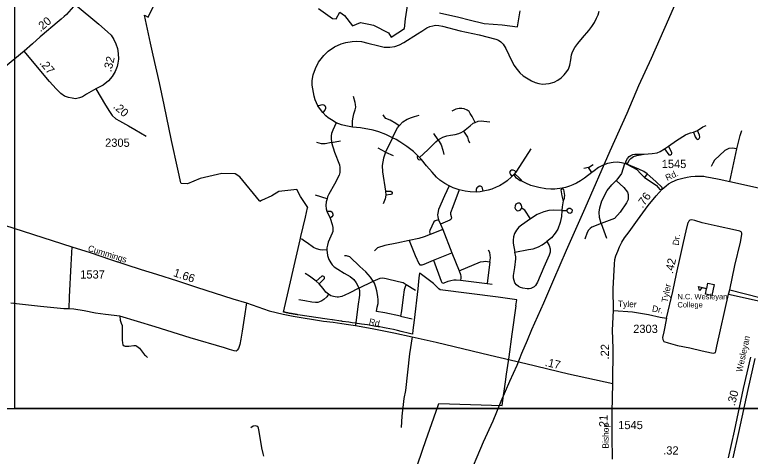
# Model space of a CAD drawing. Extents: x 2220236 to 2384410, y 720751 to 894131.
# Drawn here: x 2352246 to 2363367, y 825303 to 831981 of the extents above; entities that cross this region are included whole.
import ezdxf

# ---------------------------------------------------------------- set-up
doc = ezdxf.new("R2010")
doc.units = 0
doc.layers.add('Default', color=7, linetype='Continuous')

msp = doc.modelspace()

# ---------------------------------------------------------------- linework, layer by layer
at = {"layer": 'Default'}
for p, q in [((2358650, 830088), (2358582, 830185)), ((2362506, 830206), (2362567, 830229)), ((2357038, 830048), (2357173, 830075)), ((2357960, 830119), (2357854, 829904)), ((2357854, 829904), (2357741, 829962)), ((2362069, 829951), (2362128, 829994)), ((2363057, 829458), (2363161, 829951)), ((2357854, 829904), (2357966, 829850)), ((2358365, 829821), (2358338, 829850)), ((2358395, 829791), (2358365, 829821)), ((2360921, 829670), (2360992, 829716)), ((2359799, 829567), (2359828, 829601)), ((2360921, 829670), (2360848, 829653)), ((2360970, 829594), (2360921, 829670)), ((2359799, 829567), (2359759, 829528)), ((2361807, 829576), (2361765, 829519)), ((2356970, 829199), (2356796, 829253)), ((2357851, 829311), (2357855, 829250)), ((2356967, 829008), (2357015, 828903)), ((2360519, 829021), (2360594, 829019)), ((2358654, 828881), (2358685, 828815)), ((2358685, 828815), (2358717, 828732)), ((2361113, 828826), (2361192, 828601)), ((2358717, 828732), (2358527, 828659)), ((2358717, 828732), (2358857, 828379)), ((2358577, 828268), (2358857, 828379)), ((2358857, 828379), (2358968, 828106)), ((2359431, 828244), (2359387, 827916)), ((2356849, 827909), (2356805, 827951)), ((2357447, 827845), (2357666, 827953)), ((2358988, 827965), (2359387, 827916)), ((2359387, 827916), (2359463, 827904)), ((2358164, 827903), (2358305, 827817)), ((2363039, 827756), (2363055, 827818)), ((2363055, 827818), (2363513, 827702)), ((2363039, 827756), (2363559, 827639)), ((2358078, 827422), (2358257, 827382))]:
    msp.add_line(p, q, dxfattribs=at)
for points in [[(2352250, 836556), (2366536, 836556), (2366536, 826026), (2352250, 826026), (2352250, 836556)], [(2358330, 825160), (2358413, 825397), (2358464, 825542), (2358523, 825713), (2358584, 825885), (2358658, 826099), (2359614, 826072), (2359636, 826221), (2359651, 826325), (2359666, 826429), (2359682, 826544), (2359711, 826744), (2359720, 826805), (2359767, 827152), (2359826, 827580), (2359823, 827580), (2359836, 827667), (2359553, 827708), (2358676, 827819), (2358658, 827837), (2358579, 827916), (2358376, 828067), (2358366, 828072), (2358358, 828004), (2358339, 827835), (2358284, 827362), (2358267, 827210), (2358260, 827150), (2358236, 827156), (2358217, 827160), (2358091, 827190), (2358034, 827204), (2357971, 827220), (2357918, 827231), (2357860, 827243), (2357814, 827252), (2357764, 827260), (2357743, 827263), (2357708, 827268), (2357580, 827289), (2357489, 827302), (2357391, 827316), (2357346, 827323), (2357300, 827330), (2357201, 827344), (2357193, 827345), (2357177, 827347), (2357049, 827366), (2357046, 827366), (2356969, 827377), (2356529, 827443), (2356526, 827444), (2356522, 827444), (2356518, 827445), (2356515, 827445), (2356512, 827446), (2356508, 827446), (2356505, 827447), (2356501, 827447), (2356498, 827448), (2356494, 827449), (2356491, 827449), (2356488, 827450), (2356484, 827450), (2356480, 827451), (2356477, 827451), (2356474, 827452), (2356470, 827453), (2356467, 827453), (2356463, 827454), (2356460, 827454), (2356456, 827455), (2356453, 827456), (2356450, 827456), (2356446, 827457), (2356443, 827457), (2356439, 827458), (2356436, 827459), (2356432, 827459), (2356429, 827460), (2356426, 827461), (2356422, 827461), (2356418, 827462), (2356415, 827463), (2356412, 827463), (2356408, 827464), (2356405, 827465), (2356402, 827465), (2356398, 827466), (2356394, 827467), (2356391, 827467), (2356388, 827468), (2356384, 827469), (2356381, 827470), (2356378, 827470), (2356374, 827471), (2356370, 827472), (2356367, 827472), (2356364, 827473), (2356360, 827474), (2356357, 827475), (2356354, 827475), (2356350, 827476), (2356346, 827477), (2356343, 827478), (2356340, 827478), (2356336, 827479), (2356333, 827480), (2356330, 827481), (2356326, 827482), (2356323, 827482), (2356319, 827483), (2356316, 827484), (2356312, 827485), (2356311, 827485), (2356563, 828577), (2356574, 828626), (2356642, 828919), (2356674, 829060), (2356676, 829066), (2356676, 829068), (2356566, 829230), (2356565, 829232), (2356510, 829340), (2356241, 829305), (2356133, 829244), (2355978, 829170), (2355954, 829158), (2355947, 829166), (2355648, 829528), (2355580, 829574), (2355377, 829581), (2355048, 829504), (2354858, 829424), (2354762, 829429), (2354760, 829437), (2354714, 829646), (2354618, 830080), (2354505, 830617), (2354434, 830953), (2354340, 831367), (2354300, 831549), (2354206, 831974), (2354263, 831946), (2355002, 833447)], [(2358330, 825160), (2358413, 825397), (2358464, 825542), (2358523, 825713), (2358584, 825885), (2358658, 826099), (2359614, 826072), (2359636, 826221), (2359651, 826325), (2359666, 826429), (2359682, 826544), (2359711, 826744), (2359720, 826805), (2359767, 827152), (2359826, 827580), (2359823, 827580), (2359836, 827667), (2359553, 827708), (2358676, 827819), (2358658, 827837), (2358579, 827916), (2358376, 828067), (2358366, 828072), (2358358, 828004), (2358339, 827835), (2358284, 827362), (2358267, 827210), (2358260, 827150), (2358236, 827156), (2358217, 827160), (2358091, 827190), (2358034, 827204), (2357971, 827220), (2357918, 827231), (2357860, 827243), (2357814, 827252), (2357764, 827260), (2357743, 827263), (2357708, 827268), (2357580, 827289), (2357489, 827302), (2357391, 827316), (2357346, 827323), (2357300, 827330), (2357201, 827344), (2357193, 827345), (2357177, 827347), (2357049, 827366), (2357046, 827366), (2356969, 827377), (2356529, 827443), (2356526, 827444), (2356522, 827444), (2356518, 827445), (2356515, 827445), (2356512, 827446), (2356508, 827446), (2356505, 827447), (2356501, 827447), (2356498, 827448), (2356494, 827449), (2356491, 827449), (2356488, 827450), (2356484, 827450), (2356480, 827451), (2356477, 827451), (2356474, 827452), (2356470, 827453), (2356467, 827453), (2356463, 827454), (2356460, 827454), (2356456, 827455), (2356453, 827456), (2356450, 827456), (2356446, 827457), (2356443, 827457), (2356439, 827458), (2356436, 827459), (2356432, 827459), (2356429, 827460), (2356426, 827461), (2356422, 827461), (2356418, 827462), (2356415, 827463), (2356412, 827463), (2356408, 827464), (2356405, 827465), (2356402, 827465), (2356398, 827466), (2356394, 827467), (2356391, 827467), (2356388, 827468), (2356384, 827469), (2356381, 827470), (2356378, 827470), (2356374, 827471), (2356370, 827472), (2356367, 827472), (2356364, 827473), (2356360, 827474), (2356357, 827475), (2356354, 827475), (2356350, 827476), (2356346, 827477), (2356343, 827478), (2356340, 827478), (2356336, 827479), (2356333, 827480), (2356330, 827481), (2356326, 827482), (2356323, 827482), (2356319, 827483), (2356316, 827484), (2356312, 827485), (2356311, 827485), (2356563, 828577), (2356574, 828626), (2356642, 828919), (2356674, 829060), (2356676, 829066), (2356676, 829068), (2356566, 829230), (2356565, 829232), (2356510, 829340), (2356241, 829305), (2356133, 829244), (2355978, 829170), (2355954, 829158), (2355947, 829166), (2355648, 829528), (2355580, 829574), (2355377, 829581), (2355048, 829504), (2354858, 829424), (2354762, 829429), (2354760, 829437), (2354714, 829646), (2354618, 830080), (2354505, 830617), (2354434, 830953), (2354340, 831367), (2354300, 831549), (2354206, 831974), (2354263, 831946), (2355002, 833447)], [(2362323, 832356), (2362132, 831914), (2361866, 831321), (2361677, 830903), (2361500, 830489), (2361243, 829918), (2360865, 829050), (2360583, 828413), (2360390, 827970), (2360239, 827619), (2360058, 827213), (2359995, 827052), (2359910, 826859), (2359836, 826678), (2359727, 826435), (2359593, 826131), (2359474, 825832), (2359330, 825515), (2359079, 824930)], [(2353159, 832136), (2353133, 832104), (2353027, 831984), (2352992, 831952), (2352948, 831913), (2352886, 831863), (2352661, 831673), (2352631, 831647), (2352514, 831539), (2352388, 831430)], [(2353159, 832136), (2353517, 831837), (2353651, 831724), (2353703, 831672), (2353745, 831607), (2353774, 831539), (2353799, 831471), (2353812, 831393), (2353817, 831310), (2353807, 831250), (2353794, 831196), (2353763, 831120), (2353721, 831049), (2353663, 830981), (2353582, 830917), (2353475, 830860)], [(2356831, 830601), (2356789, 830696), (2356772, 830748), (2356753, 830860), (2356745, 830915), (2356745, 830985), (2356756, 831073), (2356792, 831170), (2356841, 831261), (2356919, 831364), (2356984, 831431), (2357080, 831495), (2357181, 831539), (2357252, 831560), (2357348, 831575), (2357415, 831580), (2357490, 831574), (2357586, 831549), (2357753, 831510), (2357832, 831492), (2357874, 831490), (2357916, 831492), (2357992, 831499), (2358066, 831526), (2358127, 831561), (2358338, 831691), (2358400, 831731), (2358477, 831785), (2358522, 831804), (2358567, 831814), (2358606, 831821), (2358656, 831819), (2358714, 831806), (2358983, 831738), (2359270, 831675), (2359519, 831613), (2359558, 831595), (2359596, 831571), (2359633, 831533), (2359670, 831471), (2359715, 831373), (2359793, 831219), (2359840, 831150), (2359881, 831101), (2359933, 831057), (2360059, 830979), (2360116, 830955), (2360172, 830941), (2360226, 830931), (2360278, 830935), (2360324, 830940), (2360402, 830963), (2360458, 830990), (2360510, 831026), (2360555, 831074), (2360595, 831123), (2360617, 831157), (2360637, 831216), (2360655, 831299), (2360666, 831373), (2360681, 831420), (2360714, 831486), (2360759, 831545), (2360832, 831633), (2360927, 831744), (2360972, 831804), (2361012, 831865), (2361041, 831927), (2361069, 831979), (2361083, 832035)], [(2356840, 832077), (2357050, 831924), (2357106, 831918), (2357162, 832021), (2357230, 831970), (2357354, 831812), (2357474, 831864), (2357598, 831838), (2357670, 831822), (2357897, 831708), (2357935, 831640), (2358140, 831773), (2358156, 831921), (2358182, 832113)], [(2356840, 832077), (2357050, 831924), (2357106, 831918), (2357162, 832021), (2357230, 831970), (2357354, 831812), (2357474, 831864), (2357598, 831838), (2357670, 831822), (2357897, 831708), (2357935, 831640), (2358140, 831773), (2358156, 831921), (2358182, 832113)], [(2358668, 832007), (2358961, 831942), (2359118, 831904), (2359344, 831850), (2359616, 831826), (2359845, 831797), (2359886, 832038)], [(2358668, 832007), (2358961, 831942), (2359118, 831904), (2359344, 831850), (2359616, 831826), (2359845, 831797), (2359886, 832038)], [(2352388, 831430), (2352108, 831200), (2351948, 831058), (2351736, 830882), (2351559, 830720), (2351415, 830571)], [(2353475, 830860), (2353331, 830777), (2353271, 830741), (2353224, 830724), (2353166, 830710), (2353117, 830717), (2353060, 830728), (2352999, 830750), (2352945, 830789), (2352871, 830858), (2352773, 830973), (2352642, 831126), (2352546, 831245), (2352388, 831430)], [(2353475, 830860), (2353555, 830722), (2353602, 830638), (2353669, 830530), (2353720, 830459), (2353777, 830407), (2353829, 830375), (2353967, 830299), (2354062, 830247), (2354232, 830143)], [(2357352, 830280), (2357355, 830374), (2357362, 830430), (2357375, 830480), (2357394, 830543), (2357404, 830584), (2357399, 830621), (2357393, 830654), (2357368, 830744)], [(2356831, 830601), (2356879, 830619), (2356899, 830625), (2356921, 830620), (2356936, 830608), (2356946, 830583), (2356946, 830561), (2356936, 830539), (2356902, 830501)], [(2356902, 830501), (2356867, 830546), (2356831, 830601)], [(2357108, 830345), (2357033, 830389), (2356983, 830423), (2356949, 830452), (2356902, 830501)], [(2359205, 830352), (2359163, 830440), (2359134, 830485), (2359117, 830516), (2359084, 830536), (2359043, 830556), (2359007, 830565), (2358965, 830563), (2358916, 830554), (2358855, 830522)], [(2358058, 830302), (2358010, 830337), (2357920, 830385), (2357857, 830410), (2357839, 830437), (2357815, 830468)], [(2358058, 830302), (2358116, 830359), (2358180, 830402), (2358244, 830429), (2358288, 830444), (2358359, 830462)], [(2359205, 830352), (2359252, 830370), (2359299, 830376), (2359338, 830373), (2359428, 830360)], [(2357108, 830345), (2357057, 830236), (2357037, 830186), (2357030, 830147), (2357028, 830113), (2357038, 830048)], [(2357352, 830280), (2357251, 830299), (2357186, 830314), (2357108, 830345)], [(2357960, 830119), (2357859, 830168), (2357753, 830209), (2357665, 830233), (2357472, 830270), (2357352, 830280)], [(2357960, 830119), (2358009, 830223), (2358034, 830268), (2358058, 830302)], [(2359029, 830219), (2359132, 830303), (2359179, 830341), (2359205, 830352)], [(2362567, 830229), (2362648, 830283), (2362699, 830308)], [(2358650, 830088), (2358717, 830128), (2358781, 830148), (2358836, 830160), (2358905, 830169), (2358960, 830185), (2358995, 830198), (2359029, 830219)], [(2359029, 830219), (2359091, 830127), (2359103, 830091), (2359120, 830042)], [(2362128, 829994), (2362252, 830078), (2362388, 830164), (2362420, 830181), (2362461, 830196), (2362506, 830206)], [(2362506, 830206), (2362532, 830136), (2362555, 830102), (2362572, 830096), (2362584, 830100), (2362596, 830111), (2362603, 830128), (2362597, 830161), (2362567, 830229)], [(2363161, 829951), (2363213, 830156), (2363237, 830230)], [(2357038, 830048), (2356938, 830030), (2356883, 830030), (2356812, 830050)], [(2357038, 830048), (2357082, 829904), (2357156, 829711), (2357161, 829671), (2357161, 829632), (2357161, 829593), (2357152, 829554), (2357082, 829416), (2356993, 829269), (2356976, 829228), (2356970, 829199)], [(2358338, 829850), (2358274, 829913), (2358176, 829987), (2358068, 830060), (2358012, 830093), (2357960, 830119)], [(2358365, 829821), (2358492, 829940), (2358613, 830061), (2358650, 830088)], [(2358650, 830088), (2358692, 830013), (2358717, 829935), (2358734, 829869)], [(2359828, 829601), (2359884, 829685), (2360055, 829953)], [(2361763, 829870), (2361883, 829881), (2361960, 829893), (2362004, 829911), (2362069, 829951)], [(2362069, 829951), (2362134, 829862), (2362159, 829862), (2362174, 829874), (2362182, 829884), (2362182, 829895), (2362128, 829994)], [(2363161, 829951), (2363094, 829962), (2363043, 829956), (2362983, 829927), (2362824, 829781), (2362798, 829737), (2362775, 829683)], [(2357854, 829904), (2357821, 829810), (2357802, 829701), (2357808, 829605), (2357851, 829311)], [(2358338, 829850), (2358331, 829826), (2358338, 829806), (2358350, 829789), (2358362, 829787), (2358395, 829791)], [(2361499, 829721), (2361486, 829748), (2361486, 829763), (2361508, 829804), (2361537, 829837), (2361559, 829854), (2361589, 829866), (2361621, 829873), (2361680, 829873), (2361763, 829870)], [(2361499, 829721), (2361517, 829738), (2361538, 829782), (2361563, 829809), (2361602, 829835), (2361653, 829851), (2361763, 829870)], [(2358813, 829391), (2358750, 829430), (2358675, 829479), (2358623, 829526), (2358555, 829599), (2358474, 829697), (2358395, 829791)], [(2361499, 829721), (2361445, 829736), (2361364, 829752), (2361295, 829745), (2361209, 829732), (2361145, 829708), (2361072, 829669), (2361004, 829622), (2360970, 829594)], [(2361466, 829726), (2361422, 829580), (2361363, 829504), (2361341, 829475)], [(2361807, 829576), (2361759, 829608), (2361684, 829646), (2361499, 829721)], [(2361499, 829721), (2361649, 829638), (2361712, 829574), (2361744, 829542), (2361765, 829519)], [(2359828, 829601), (2359807, 829622), (2359781, 829631), (2359758, 829629), (2359740, 829619), (2359728, 829599), (2359730, 829584), (2359740, 829567), (2359750, 829549), (2359759, 829528)], [(2360970, 829594), (2360862, 829511), (2360798, 829467), (2360739, 829431), (2360685, 829407), (2360632, 829389), (2360573, 829369), (2360522, 829356)], [(2359759, 829528), (2359693, 829469), (2359640, 829431), (2359575, 829394), (2359527, 829373), (2359460, 829345), (2359403, 829327), (2359329, 829313)], [(2359914, 829466), (2359907, 829480), (2359870, 829521), (2359818, 829564), (2359799, 829567)], [(2359914, 829466), (2359890, 829471), (2359834, 829511), (2359807, 829538), (2359799, 829567)], [(2361113, 828826), (2361089, 828915), (2361084, 828994), (2361093, 829060), (2361122, 829165), (2361201, 829324), (2361272, 829407), (2361341, 829475)], [(2361341, 829475), (2361455, 829369), (2361511, 829299), (2361522, 829261), (2361522, 829188), (2361497, 829136), (2361402, 828996), (2361312, 828897), (2361272, 828882), (2361113, 828826)], [(2361301, 827510), (2361294, 827837), (2361314, 828209), (2361320, 828278), (2361336, 828333), (2361362, 828406), (2361388, 828471), (2361426, 828540), (2361466, 828609), (2361534, 828697), (2361662, 828875), (2361821, 829098), (2361943, 829242), (2362032, 829343), (2362094, 829394), (2362132, 829422), (2362188, 829453), (2362267, 829488), (2362349, 829511), (2362411, 829525), (2362467, 829532), (2362533, 829539), (2362578, 829539), (2362614, 829540), (2362664, 829538), (2362704, 829530), (2362766, 829520), (2362897, 829494), (2363057, 829458), (2363853, 829280)], [(2361765, 829519), (2361868, 829455), (2361948, 829398), (2361997, 829340), (2362032, 829343)], [(2362032, 829343), (2362032, 829366), (2361937, 829460), (2361855, 829536), (2361807, 829576)], [(2358813, 829391), (2358742, 829244), (2358654, 829036), (2358642, 828982), (2358639, 828956), (2358641, 828926), (2358654, 828881)], [(2358965, 829331), (2358877, 829364), (2358813, 829391)], [(2359329, 829313), (2359320, 829356), (2359307, 829377), (2359290, 829387), (2359268, 829387), (2359246, 829375), (2359232, 829363), (2359222, 829338), (2359225, 829298)], [(2360522, 829356), (2360413, 829343), (2360349, 829343), (2360276, 829350), (2360170, 829368), (2360051, 829397), (2359973, 829431), (2359914, 829466)], [(2357855, 829250), (2357848, 829195), (2357816, 829123)], [(2357851, 829311), (2357934, 829313), (2357951, 829297), (2357955, 829281), (2357949, 829269), (2357934, 829262), (2357855, 829250)], [(2358965, 829331), (2358869, 829074), (2358836, 828986), (2358834, 828965), (2358846, 828927), (2358850, 828905), (2358841, 828886), (2358823, 828873), (2358685, 828815)], [(2359225, 829298), (2359133, 829303), (2359057, 829310), (2358965, 829331)], [(2359329, 829313), (2359281, 829304), (2359225, 829298)], [(2360522, 829356), (2360502, 829335), (2360519, 829240), (2360531, 829183), (2360539, 829167)], [(2360522, 829356), (2360541, 829339), (2360556, 829249), (2360554, 829224), (2360551, 829198), (2360539, 829167)], [(2356970, 829199), (2356955, 829150), (2356951, 829097), (2356957, 829045), (2356967, 829008)], [(2360539, 829167), (2360524, 829077), (2360519, 829021)], [(2360043, 828892), (2359960, 829023), (2359934, 829041), (2359911, 829054)], [(2360519, 829021), (2360388, 829025), (2360319, 829018), (2360248, 829001), (2360147, 828958), (2360043, 828892)], [(2356967, 829008), (2357002, 829011), (2357027, 829009), (2357047, 828994), (2357057, 828966), (2357057, 828947), (2357042, 828923), (2357015, 828903)], [(2360519, 829021), (2360513, 828929), (2360494, 828841), (2360456, 828740), (2360419, 828675), (2360359, 828608), (2360293, 828549)], [(2351931, 828849), (2353109, 828472), (2353387, 828383), (2353695, 828279), (2354158, 828130), (2354389, 828058), (2354709, 827954), (2354994, 827862), (2355545, 827685), (2355750, 827623), (2356092, 827503), (2356307, 827452), (2356456, 827420), (2356606, 827398), (2356764, 827373), (2356916, 827349), (2357061, 827330), (2357193, 827313), (2357292, 827297), (2357398, 827279), (2357651, 827238), (2357977, 827172), (2358253, 827112), (2358616, 827028), (2359432, 826831), (2359974, 826705), (2360617, 826552), (2361288, 826402)], [(2357015, 828903), (2357047, 828808), (2357054, 828761), (2357054, 828727), (2357054, 828705), (2357047, 828675), (2356987, 828543), (2356973, 828494), (2356965, 828458), (2356967, 828426)], [(2358654, 828881), (2358604, 828863), (2358582, 828848), (2358520, 828718), (2358516, 828695), (2358527, 828659)], [(2360043, 828892), (2359907, 828800), (2359870, 828767), (2359834, 828725), (2359804, 828673), (2359789, 828622), (2359784, 828573), (2359784, 828526), (2359809, 828390)], [(2361113, 828826), (2360973, 828770), (2360944, 828746), (2360919, 828723), (2360899, 828686), (2360863, 828587)], [(2361301, 827510), (2361586, 827490), (2361826, 827447), (2362002, 827408), (2362101, 827391), (2362196, 827797), (2362252, 828063), (2362305, 828310), (2362359, 828537), (2362399, 828711), (2362430, 828839)], [(2363055, 827818), (2363135, 828188), (2363217, 828541), (2363240, 828655), (2363238, 828677), (2363227, 828697), (2363207, 828707), (2363141, 828724), (2362868, 828783), (2362639, 828836), (2362527, 828868), (2362483, 828878), (2362454, 828875), (2362438, 828858), (2362430, 828839)], [(2356967, 828426), (2356904, 828421), (2356863, 828424), (2356808, 828441), (2356763, 828463), (2356670, 828532), (2356611, 828568), (2356580, 828593)], [(2358527, 828659), (2358437, 828620), (2358355, 828597), (2358209, 828568)], [(2353109, 828472), (2353094, 828197), (2353069, 827716), (2353067, 827534)], [(2358209, 828568), (2358021, 828528), (2357842, 828490), (2357731, 828454), (2357686, 828410)], [(2358209, 828568), (2358301, 828341), (2358358, 828217), (2358372, 828199), (2358404, 828196), (2358434, 828209), (2358577, 828268)], [(2360293, 828549), (2360325, 828492), (2360340, 828438), (2360340, 828388), (2360326, 828343), (2360245, 828161), (2360150, 827935), (2360118, 827886), (2360097, 827864), (2360069, 827849), (2360050, 827843), (2360023, 827837), (2359993, 827837), (2359927, 827845), (2359891, 827856), (2359864, 827871), (2359834, 827894), (2359809, 827928), (2359796, 827961), (2359788, 827995), (2359788, 828038), (2359805, 828160), (2359821, 828291), (2359821, 828320), (2359809, 828390)], [(2359809, 828390), (2360013, 828428), (2360085, 828442), (2360166, 828470), (2360220, 828500), (2360293, 828549)], [(2356967, 828426), (2356975, 828341), (2356995, 828279), (2357025, 828230), (2357047, 828199), (2357078, 828169), (2357130, 828132), (2357225, 828073), (2357318, 828020), (2357371, 827978), (2357410, 827928), (2357427, 827890), (2357447, 827845)], [(2359431, 828244), (2359439, 828302), (2359436, 828345), (2359427, 828385), (2359410, 828419)], [(2357666, 827953), (2357625, 828013), (2357554, 828094), (2357466, 828175), (2357313, 828318), (2357264, 828333), (2357232, 828335)], [(2358577, 828268), (2358694, 827949), (2358705, 827932), (2358722, 827922), (2358738, 827924), (2358801, 827949), (2358840, 827963), (2358885, 827970), (2358921, 827970), (2358988, 827965)], [(2358968, 828106), (2359290, 828242), (2359331, 828249), (2359360, 828253), (2359431, 828244)], [(2356805, 827951), (2356704, 828025), (2356635, 828066)], [(2356849, 827909), (2356930, 827992), (2356930, 828010), (2356920, 828024), (2356905, 828028), (2356891, 828025), (2356805, 827951)], [(2358968, 828106), (2358985, 828054), (2358990, 828020), (2358990, 827998), (2358988, 827965)], [(2357666, 827953), (2357770, 827996), (2357812, 828002), (2357861, 827990), (2358050, 827948), (2358117, 827929), (2358164, 827903)], [(2357715, 827492), (2357727, 827559), (2357739, 827615), (2357742, 827667), (2357737, 827719), (2357723, 827803), (2357707, 827862), (2357685, 827919), (2357666, 827953)], [(2356990, 827753), (2356952, 827787), (2356907, 827840), (2356849, 827909)], [(2357447, 827845), (2357302, 827772), (2357235, 827738), (2357193, 827721), (2357169, 827716), (2357142, 827712), (2357119, 827711), (2357092, 827713), (2357066, 827718), (2357027, 827730), (2356990, 827753)], [(2357447, 827845), (2357458, 827812), (2357461, 827739), (2357436, 827567), (2357398, 827279)], [(2358164, 827903), (2358151, 827864), (2358134, 827818), (2358117, 827710), (2358092, 827501), (2358078, 827422)], [(2356990, 827753), (2356963, 827713), (2356921, 827675), (2356887, 827653), (2356854, 827638), (2356829, 827631), (2356796, 827629), (2356738, 827636), (2356634, 827656), (2356540, 827671)], [(2362101, 827391), (2362059, 827183), (2362042, 827100), (2362044, 827071), (2362061, 827041), (2362127, 827017), (2362268, 826981), (2362455, 826942), (2362637, 826898), (2362781, 826866), (2362810, 826864), (2362841, 826875), (2362845, 826894), (2362850, 826916), (2362860, 826970), (2363039, 827756)], [(2353067, 827534), (2352990, 827531), (2352635, 827570), (2352320, 827604), (2352187, 827617)], [(2355750, 827623), (2355716, 827390), (2355683, 827195), (2355665, 827072), (2355652, 826995), (2355631, 826935), (2355610, 826906), (2355594, 826893), (2355565, 826896), (2355493, 826917), (2355416, 826942), (2354898, 827095), (2354372, 827262), (2353837, 827420)], [(2353837, 827420), (2353619, 827447), (2353466, 827470), (2353294, 827505), (2353140, 827528), (2353067, 827534)], [(2358078, 827422), (2357842, 827471), (2357715, 827492)], [(2361288, 826402), (2361292, 826931), (2361286, 827211), (2361301, 827510)], [(2353837, 827420), (2353841, 827363), (2353856, 827317), (2353869, 827282), (2353873, 827227), (2353872, 827182), (2353873, 827060), (2353876, 827019), (2353882, 826991), (2353900, 826975), (2353918, 826967), (2353946, 826967), (2353970, 826966), (2354048, 826979), (2354076, 826979), (2354092, 826971), (2354131, 826940), (2354147, 826916), (2354210, 826837), (2354226, 826825), (2354252, 826799)], [(2358253, 827112), (2358217, 826851), (2358155, 826298), (2358131, 826176), (2358100, 825908), (2358091, 825740)], [(2363372, 826803), (2363261, 826327), (2363121, 825684), (2363030, 825278)], [(2363106, 825279), (2363194, 825665), (2363336, 826312), (2363440, 826784)], [(2361282, 825260), (2361280, 825604), (2361279, 825971), (2361288, 826402)], [(2346104, 826027), (2370568, 826027), (2370568, 816975), (2346104, 816975), (2346104, 826027)], [(2356014, 825303), (2356001, 825343), (2355984, 825432), (2355943, 825676), (2355932, 825730), (2355920, 825754), (2355904, 825761), (2355894, 825763), (2355852, 825757), (2355817, 825736)]]:
    msp.add_lwpolyline(points, dxfattribs=at)
for points in [[(2359911, 829054), (2359914, 829078), (2359909, 829103), (2359894, 829123), (2359877, 829130), (2359851, 829132), (2359822, 829117), (2359810, 829092), (2359807, 829060), (2359816, 829039), (2359838, 829022), (2359854, 829016), (2359873, 829018), (2359890, 829025)], [(2360594, 829019), (2360606, 829043), (2360624, 829054), (2360645, 829054), (2360660, 829047), (2360672, 829029), (2360675, 829012), (2360668, 828998), (2360658, 828985), (2360638, 828977), (2360621, 828980), (2360606, 828991)], [(2362785, 827734), (2362689, 827754), (2362706, 827834), (2362633, 827849), (2362599, 827808), (2362583, 827870), (2362708, 827843), (2362725, 827922), (2362821, 827902)]]:
    msp.add_lwpolyline(points, close=True, dxfattribs=at)

# ---------------------------------------------------------------- texts
for s, height, rotation, p in [('.20', 125, 40.3378, (2352635, 831715)), ('.27', 125, 310.1819, (2352615, 831245)), ('.32', 125, 76.6572, (2353706, 831108)), ('.20', 125, 317.858, (2353726, 830580)), ('Rd.', 95, 25.6153, (2362111, 829466)), ('.76', 125, 54.4896, (2361739, 829048)), ('Dr.', 95, 82.5267, (2362285, 828488)), ('Cummings', 95, 342.7168, (2353345, 828409)), ('.42', 125, 77.6279, (2362196, 828056)), ('1.66', 125, 341.2947, (2354636, 828030)), ('Tyler', 95, 78.9403, (2362116, 827624)), ('Tyler', 95, 357.6798, (2361365, 827565)), ('Dr.', 95, 349.4061, (2361876, 827495)), ('Rd.', 95, 346.2787, (2357594, 827299)), ('Wesleyan', 95, 77.4919, (2363243, 826569)), ('.22', 125, 88.8853, (2361228, 826766)), ('.17', 125, 347.2702, (2360255, 826671)), ('.30', 125, 74.7097, (2363131, 826058)), ('.21', 125, 88.5743, (2361205, 825697)), ('Bishop', 95, 89.0448, (2361224, 825419)), ('.32', 125, 359.1943, (2362049, 825331))]:
    msp.add_text(s, height=height, rotation=rotation, dxfattribs=at).set_placement(p)
for s, height, p in [('2305', 125, (2353613, 829983)), ('1545', 125, (2362028, 829662)), ('1537', 125, (2353237, 827991)), ('N.C. Wesleyan', 82.02, (2362265, 827677)), ('College', 82, (2362265, 827554)), ('2303', 125, (2361597, 827168)), ('1545', 125, (2361370, 825714))]:
    msp.add_text(s, height=height, dxfattribs=at).set_placement(p)

doc.saveas('drawing.dxf')
